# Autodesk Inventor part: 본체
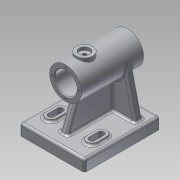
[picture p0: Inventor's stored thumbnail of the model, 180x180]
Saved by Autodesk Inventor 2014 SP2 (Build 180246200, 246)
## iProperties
Created: 2022-06
Part Number: 본체
Material: 알루미늄 6061
Document SubType Name: Modeling
Designer: 거성
Density: 2.71 g/cm^3
Appearance: 알루미늄 - 평지
Mass: 633.96 g
Surface Area: 512.727 cm^2
Volume: 233.934 cm^3
Author: 거성
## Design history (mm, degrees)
sketch "스케치1"
  geometry: L1 (0, 41)-(0, -41); L2 (14.5, 41)-(14.5, -21); L3 (14.5, -21)-(11.5, -21); L4 (11.5, -21)-(11.5, -41); L5 (11.5, -41)-(21, -41); L6 (21, -41)-(21, 41); L7 (21, 41)-(14.5, 41); 2 further points
  constraints: 14 end point, 5 parallel, 2 horizontal alignment, 1 coincident, 1 midpoint, 1 perpendicular, 1 vertical
  dimensions: "d0" = 82 distance of L1.start L1.end; "d1" = 29 diameter of L2 L1; "d2" = 23 diameter of L4 L1; "d3" = 42 diameter of L6 L1; "d4" = 62 distance of L2.start L2.end
revolve "회전1" sketch "스케치1" stored, may be unused: angle "d5" = 90 deg
node "작업 평면1"
sketch "스케치2"
  geometry: L1 (43, 59)-(-43, 59); L2 (-43, 59)-(-43, -41); L3 (-43, -41)-(43, -41); L4 (43, -41)-(43, 59); L5 (43, 59)-(-43, -41); L6 (-43, 59)-(43, -41); L7 (-21, 41)-(21, 41) reference; 3 further points
  constraints: 12 end point, 3 midpoint, 2 parallel, 1 horizontal, 1 perpendicular, 1 vertical alignment
  dimensions: "d7" = 86 distance of L3.end L2.end; "d8" = 100 distance of L2.end L1.end; "d9" = 18 distance between parallel lines of L1 L7
extrude "돌출1" join sketch "스케치2" distance "d10" = 15; taper "d11" = 0 deg
fillet "모깎기1" dims "d12" = 3
node "작업 평면2"
sketch "스케치3"
  geometry: L1 (-40, -57)-(40, -57) reference; L2 (-20.441, 4.814)-(-35, -57); L3 (20.441, 4.814)-(35, -57); L4 (43, -60)-(43, -72) reference; L5 (-43, -72)-(-43, -60) reference; C1 r 14.5 at (0, 0) reference; A1 r 21 centre (0, 0) between (-20.441, 4.814) and (20.441, 4.814) reference; 1 further point
  constraints: 4 end point, 2 point on circle, 2 point on line, 1 horizontal alignment, 1 tangent
  dimensions: "d14" = 8 distance from line of L4 L3.end; "d15" = 8 distance from line of L5 L2.end
extrude "돌출2" join sketch "스케치3" distance "d16" = 10; taper "d17" = 0 deg
node "작업 평면3"
sketch "스케치4"
  geometry: L1 (14.5, 41)-(21, 41) reference; L2 (21, 41)-(21, -41) reference; L3 (21, -41)-(11.5, -41) reference; L4 (11.5, -41)-(11.5, -21) reference; L5 (11.5, -21)-(14.5, -21) reference; L6 (14.5, -21)-(14.5, 41) reference; L7 (-57, 56)-(-57, -16) reference; L8 (-57, -16)-(-21, -16) reference; L9 (-21, -16)-(-21, 41) reference; L10 (-21, 41)-(-14.5, 41) reference; L11 (-14.5, 41)-(-14.5, -21) reference; L12 (-14.5, -21)-(-11.5, -21) reference; L13 (-11.5, -21)-(-11.5, -41) reference; L14 (-11.5, -41)-(-21, -41) reference; L15 (-21, -41)-(-21, -26) reference; L16 (-21, -26)-(-57, -26) reference; L17 (-57, -26)-(-57, -38) reference; L18 (-60, -41)-(-72, -41) reference; L19 (-72, -41)-(-72, 59) reference; L20 (-72, 59)-(-60, 59) reference; L21 (-57, 56)-(-57, -38) reference; L22 (-21, 41)-(-21, -41) reference; L23 (-57, 44)-(-21, 30.897); A1 r 3 centre (-60, 56) between (-57, 56) and (-60, 59) reference; A2 r 3 centre (-60, -38) between (-60, -41) and (-57, -38) reference; 1 further point
  constraints: 2 end point, 2 point on line
  dimensions: "d19" = 70 deg angle of L7 L23; "d20" = 15 distance from line of L23.start L20
feature "리브1" sketch "스케치4" dims "d21" = 1, "d22" = 10, "d23" = 0, "d24" = 0, "d25" = 1, "d26" = 1
fillet "모깎기2" dims "d27" = 3
fillet "모깎기3" dims "d28" = 3
node "작업 평면4"
sketch "스케치5"
  geometry: L1 (-21, 41)-(21, 41) reference; C1 r 11 at (0, 16); C2 r 7 at (0, 16); 1 further point
  constraints: 2 centre point, 1 coincident, 1 vertical alignment
  dimensions: "d30" = 22 diameter of C1; "d31" = 14 diameter of C2; "d32" = 25 distance from line of C2.centre L1
node "작업 평면5"
sketch "스케치6"
  geometry: L1 (-27, -33)-(-27, -21); L2 (-20, -33)-(-20, -21); L3 (-34, -21)-(-34, -33); L4 (-27, -33)-(-27, -21); L5 (-23, -33)-(-23, -21); L6 (-31, -21)-(-31, -33); L7 (-40, -59)-(40, -59) reference; A1 r 7 centre (-27, -33) between (-34, -33) and (-20, -33); A2 r 7 centre (-27, -21) between (-20, -21) and (-34, -21); A3 r 4 centre (-27, -33) between (-31, -33) and (-23, -33); A4 r 4 centre (-27, -21) between (-23, -21) and (-31, -21); 3 further points
  constraints: 16 end point, 8 point on circle, 8 tangent, 4 centre point, 3 equal length, 2 midpoint, 1 vertical
  dimensions: "d42" = 12 distance of L1.start L1.end; "d43" = 14 diameter of A2; "d44" = 8 diameter of A4; "d45" = 27 horizontal distance of point (0, 0) point (-27, -27); "d63" = 26 distance from line of L7 L1.start
extrude "돌출5" join sketch "스케치6" stored distance "d47" = 10; taper "d48" = 0 deg
extrude "돌출6" cut sketch "스케치6" stored distance "d49" = 10; taper "d50" = 0 deg
fillet "모깎기5" dims "d51" = 3
sketch "스케치7"
  geometry: L1 (-40, -56)-(-40, 38) reference; L2 (27, -33)-(27, -21); L3 (34, -33)-(34, -21); L4 (20, -21)-(20, -33); L5 (27, -33)-(27, -21); L6 (31, -33)-(31, -21); L7 (23, -21)-(23, -33); L8 (-40, -59)-(40, -59) reference; A1 r 7 centre (27, -33) between (20, -33) and (34, -33); A2 r 7 centre (27, -21) between (34, -21) and (20, -21); A3 r 4 centre (27, -33) between (23, -33) and (31, -33); A4 r 4 centre (27, -21) between (31, -21) and (23, -21); 3 further points
  constraints: 16 end point, 8 point on circle, 8 tangent, 4 centre point, 3 parallel, 2 midpoint, 1 collinear
  dimensions: "d52" = 12 distance of L2.start L2.end; "d53" = 14 diameter of A2; "d54" = 8 diameter of A4; "d55" = 27 horizontal distance of point (0, 0) point (27, -27); "d57" = 26 distance from line of L8 L2.start
extrude "돌출7" join sketch "스케치7" distance "d58" = 3; taper "d59" = 0 deg
extrude "돌출8" cut sketch "스케치7" stored distance "d60" = 3; taper "d61" = 0 deg
fillet "모깎기6" dims "d62" = 3
sketch "스케치8" dims "d64" = 36
  geometry: L1 (0, 0)-(0, 18); C1 r 21 at (0, 0) reference; 1 further point
  constraints: 2 coincident, 2 end point, 1 vertical, 1 vertical alignment, 2 other
hole "구멍1" sketch "스케치8" at (0, 18) diameter "d65" = 2.459; stored, may be unused: countersink angle "d69" = 90 deg, drill point angle "d71" = 118 deg; dims "d66" = 8, "d67" = 4, "d68" = 2, "d70" = 10
sketch "스케치9" dims "d75" = 36
  geometry: L1 (0, 0)-(0, 18); C1 r 21 at (0, 0) reference
  constraints: 2 end point, 1 coincident, 1 vertical, 1 vertical alignment, 2 other
hole "구멍2" sketch "스케치9" at (0, 18) diameter "d76" = 2.459; stored, may be unused: countersink angle "d80" = 90 deg, drill point angle "d82" = 118 deg; dims "d77" = 8, "d78" = 4, "d79" = 2, "d81" = 10
sketch "스케치10"
  geometry: L1 (0, 0)-(80, 0) reference; 2 further points
  constraints: 1 vertical alignment, 1 other
  dimensions: "d86" = 6 distance from line of L1 point (40, 6)
feature "엠보싱1" sketch "스케치10" dims "d0" = 82, "d1" = 29, "d2" = 23, "d3" = 42, "d4" = 62, "d87" = 0.5, "d88" = 0
chamfer "모따기1" distance "d89" = 1; stored, may be unused: second distance "d90" = 2, angle "d91" = 45 deg
chamfer "모따기2" distance "d92" = 1; stored, may be unused: second distance "d93" = 2, angle "d94" = 45 deg
extrude "돌출9" join sketch "스케치5" stored distance "d95" = 4; taper "d96" = 0 deg
sketch "스케치11"
  geometry: C1 r 11 at (0, 0) reference; C2 r 7 at (0, 0); 1 further point
  constraints: 1 centre point, 1 coincident
  dimensions: "d97" = 14 diameter of C2
extrude "돌출10" cut sketch "스케치11" distance "d98" = 4; taper "d99" = 0 deg
sketch "스케치12"
  geometry: C1 r 7 at (0, 0) reference; 2 further points
  constraints: 1 coincident
hole "구멍3" sketch "스케치12" at (0, 0) diameter "d100" = 4.917; stored, may be unused: countersink angle "d104" = 90 deg, drill point angle "d106" = 0 deg; dims "d101" = 8, "d102" = 4, "d103" = 2, "d105" = 6
node "솔리드1"
pattern_circular "원형 패턴1" dims angle "d73" = 360 deg
pattern_circular "원형 패턴2" dims angle "d84" = 360 deg
node "투영된 루프1"
node "절단 모서리 투영1"
other parameters: "d6" = -72, "d13" = -15, "d18" = 0, "d29" = 24, "d38" = 3
